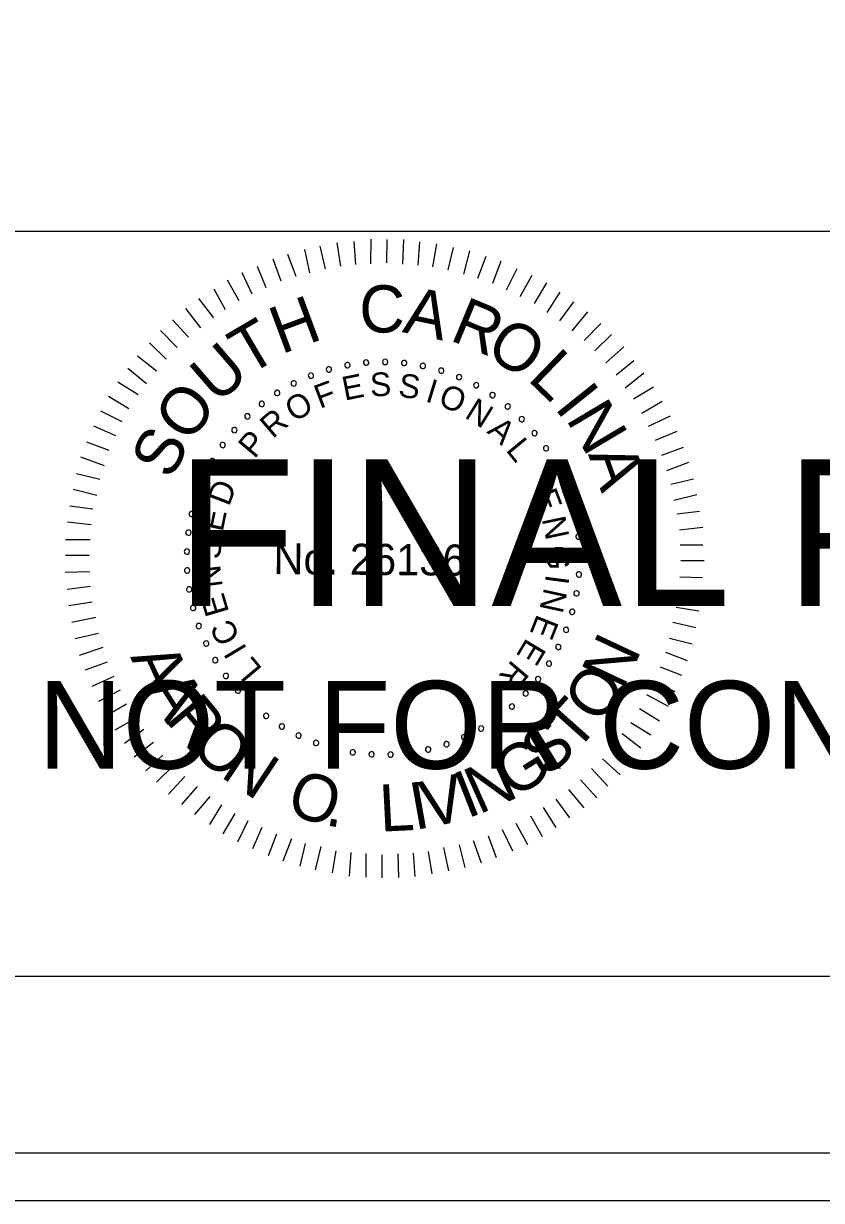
# Model space of a CAD drawing. Extents: x 967 to 1326, y 964 to 3704.
# Drawn here: x 1170.56 to 1189.3, y 1803.72 to 1831.36 of the extents above; entities that cross this region are included whole.
import ezdxf

# ---------------------------------------------------------------- set-up
doc = ezdxf.new("R2010")
doc.units = 0
for name, color, linetype in [('RD_SHT_Bndy', 7, 'Continuous'), ('RD_SHT_IplotShp', 7, 'Continuous'), ('RD_SHT_Misc1', 7, 'Continuous'), ('RD_SHT_Misc2', 7, 'Continuous'), ('RD_XS_TX_Station', 7, 'Continuous')]:
    doc.layers.add(name, color=color, linetype=linetype)

msp = doc.modelspace()

# ---------------------------------------------------------------- linework, layer by layer
at = {"layer": 'RD_SHT_Bndy'}
for p, q in [((996.114, 1826.486), (1323.886, 1826.486)), ((1323.886, 1808.983), (996.114, 1808.983))]:
    msp.add_line(p, q, dxfattribs=at)
at = {"layer": 'RD_SHT_IplotShp'}
for points in [[(967.409, 1803.72), (1326.285, 1803.72), (1326.285, 2023.72), (967.409, 2023.72)], [(988.525, 1804.84), (1326.285, 1804.84), (1326.285, 2022.6), (988.525, 2022.6)]]:
    msp.add_lwpolyline(points, close=True, dxfattribs=at)
at = {"layer": 'RD_SHT_Misc1'}
for p, q in [((1178.01, 1825.663), (1177.93, 1826.209)), ((1178.364, 1825.699), (1178.33, 1826.244)), ((1178.717, 1825.719), (1178.722, 1826.295)), ((1179.093, 1825.739), (1179.098, 1826.292)), ((1179.469, 1825.713), (1179.489, 1826.288)), ((1179.829, 1825.687), (1179.872, 1826.231)), ((1180.174, 1825.646), (1180.271, 1826.19)), ((1176.964, 1825.419), (1176.769, 1825.935)), ((1177.287, 1825.508), (1177.169, 1826.054)), ((1177.657, 1825.597), (1177.53, 1826.128)), ((1180.535, 1825.573), (1180.662, 1826.102)), ((1180.902, 1825.478), (1181.045, 1826.022)), ((1181.231, 1825.384), (1181.428, 1825.896)), ((1176.264, 1825.156), (1176.053, 1825.657)), ((1176.61, 1825.306), (1176.423, 1825.83)), ((1181.584, 1825.265), (1181.78, 1825.786)), ((1181.905, 1825.109), (1182.154, 1825.606)), ((1175.624, 1824.846), (1175.352, 1825.332)), ((1175.933, 1825.005), (1175.699, 1825.506)), ((1182.226, 1824.953), (1182.506, 1825.45)), ((1175.308, 1824.634), (1175.036, 1825.12)), ((1182.562, 1824.789), (1182.85, 1825.27)), ((1175.03, 1824.445), (1174.681, 1824.9)), ((1182.86, 1824.572), (1183.163, 1825.053)), ((1183.158, 1824.378), (1183.484, 1824.828)), ((1174.729, 1824.217), (1174.372, 1824.665)), ((1183.447, 1824.145), (1183.811, 1824.587)), ((1174.435, 1823.997), (1174.062, 1824.399)), ((1183.729, 1823.92), (1184.116, 1824.316)), ((1174.172, 1823.753), (1173.776, 1824.148)), ((1183.98, 1823.672), (1184.368, 1824.061)), ((1173.909, 1823.479), (1173.52, 1823.858)), ((1184.232, 1823.394), (1184.657, 1823.767)), ((1173.684, 1823.197), (1173.242, 1823.546)), ((1184.475, 1823.108), (1184.892, 1823.45)), ((1173.451, 1822.9), (1173.009, 1823.256)), ((1184.687, 1822.807), (1185.128, 1823.156)), ((1173.257, 1822.64), (1172.776, 1822.936)), ((1173.039, 1822.312), (1172.559, 1822.6)), ((1184.885, 1822.544), (1185.355, 1822.832)), ((1185.081, 1822.213), (1185.56, 1822.493)), ((1172.883, 1822.006), (1172.379, 1822.256)), ((1185.24, 1821.904), (1185.756, 1822.145)), ((1172.727, 1821.677), (1172.215, 1821.904)), ((1185.399, 1821.573), (1185.907, 1821.791)), ((1172.571, 1821.333), (1172.051, 1821.53)), ((1185.549, 1821.226), (1186.057, 1821.414)), ((1172.461, 1820.974), (1171.91, 1821.178)), ((1185.669, 1820.865), (1186.185, 1821.06)), ((1172.351, 1820.652), (1171.807, 1820.787)), ((1185.759, 1820.541), (1186.297, 1820.667)), ((1172.286, 1820.276), (1171.727, 1820.419)), ((1185.832, 1820.165), (1186.371, 1820.298)), ((1172.191, 1819.955), (1171.647, 1820.029)), ((1185.906, 1819.842), (1186.436, 1819.906)), ((1172.15, 1819.587), (1171.598, 1819.653)), ((1185.964, 1819.473), (1186.51, 1819.53)), ((1172.124, 1819.234), (1171.548, 1819.239)), ((1185.977, 1819.12), (1186.514, 1819.115)), ((1172.105, 1818.866), (1171.545, 1818.871)), ((1185.997, 1818.751), (1186.542, 1818.747)), ((1172.118, 1818.482), (1171.542, 1818.471)), ((1185.971, 1818.368), (1186.508, 1818.348)), ((1172.138, 1818.136), (1171.585, 1818.072)), ((1185.952, 1818.022), (1186.497, 1817.949)), ((1172.173, 1817.768), (1171.627, 1817.688)), ((1185.888, 1817.655), (1186.417, 1817.566)), ((1172.262, 1817.414), (1171.701, 1817.296)), ((1185.808, 1817.302), (1186.345, 1817.175)), ((1172.321, 1817.037), (1171.774, 1816.911)), ((1185.729, 1816.926), (1186.265, 1816.792)), ((1172.425, 1816.707), (1171.871, 1816.519)), ((1185.634, 1816.597), (1186.146, 1816.401)), ((1172.53, 1816.36), (1172.007, 1816.173)), ((1185.508, 1816.253), (1186.013, 1816.057)), ((1172.681, 1816.029), (1172.165, 1815.788)), ((1172.831, 1815.705), (1172.323, 1815.441)), ((1185.352, 1815.924), (1185.857, 1815.675)), ((1185.188, 1815.603), (1185.7, 1815.33)), ((1172.982, 1815.374), (1172.497, 1815.094)), ((1185.024, 1815.274), (1185.498, 1814.987)), ((1173.194, 1815.042), (1172.709, 1814.762)), ((1184.822, 1814.946), (1185.288, 1814.658)), ((1173.384, 1814.78), (1172.936, 1814.453)), ((1184.62, 1814.687), (1185.055, 1814.353)), ((1173.612, 1814.478), (1173.164, 1814.129)), ((1184.403, 1814.389), (1184.814, 1814.033)), ((1173.832, 1814.177), (1173.437, 1813.812)), ((1184.155, 1814.092), (1184.574, 1813.72)), ((1174.091, 1813.945), (1173.689, 1813.541)), ((1183.899, 1813.864), (1184.28, 1813.454)), ((1174.35, 1813.674), (1173.97, 1813.263)), ((1183.644, 1813.597), (1184.024, 1813.18)), ((1174.64, 1813.442), (1174.275, 1813.022)), ((1174.937, 1813.209), (1174.58, 1812.782)), ((1183.358, 1813.37), (1183.715, 1812.944)), ((1175.212, 1813.014), (1174.932, 1812.549)), ((1182.764, 1812.952), (1183.059, 1812.482)), ((1183.065, 1813.141), (1183.384, 1812.709)), ((1175.525, 1812.812), (1175.245, 1812.331)), ((1175.83, 1812.633), (1175.588, 1812.136)), ((1182.463, 1812.755), (1182.743, 1812.269)), ((1176.159, 1812.477), (1175.94, 1811.98)), ((1181.8, 1812.431), (1182.041, 1811.93)), ((1182.124, 1812.581), (1182.396, 1812.08)), ((1176.503, 1812.321), (1176.307, 1811.816)), ((1176.855, 1812.211), (1176.651, 1811.69)), ((1177.177, 1812.1), (1177.05, 1811.572)), ((1180.791, 1812.07), (1180.926, 1811.54)), ((1181.122, 1812.175), (1181.31, 1811.652)), ((1181.476, 1812.28), (1181.664, 1811.771)), ((1177.545, 1812.036), (1177.409, 1811.484)), ((1177.897, 1811.933), (1177.808, 1811.412)), ((1178.25, 1811.892), (1178.207, 1811.34)), ((1178.603, 1811.866), (1178.598, 1811.313)), ((1178.978, 1811.84), (1178.974, 1811.295)), ((1179.355, 1811.86), (1179.365, 1811.307)), ((1179.715, 1811.88), (1179.749, 1811.327)), ((1180.061, 1811.915), (1180.149, 1811.393)), ((1180.423, 1812.012), (1180.541, 1811.458))]:
    msp.add_line(p, q, dxfattribs=at)
for centre, start, end in [((1178.168, 1823.337), 10.6038, 190.6038), ((1178.609, 1823.397), 5.0653, 185.0653), ((1178.609, 1823.397), 185.0653, 5.0653), ((1179.055, 1823.414), 359.5268, 179.5268), ((1179.055, 1823.414), 179.5268, 359.5268), ((1179.5, 1823.388), 353.9884, 173.9884), ((1177.312, 1823.091), 21.6807, 201.6807), ((1177.734, 1823.235), 16.1422, 196.1422), ((1177.734, 1823.235), 196.1422, 16.1422), ((1178.168, 1823.337), 190.6038, 10.6038), ((1179.5, 1823.388), 173.9884, 353.9884), ((1179.94, 1823.319), 168.4499, 348.4499), ((1179.94, 1823.319), 348.4499, 168.4499), ((1180.372, 1823.208), 162.9114, 342.9114), ((1180.372, 1823.208), 342.9114, 162.9114), ((1180.79, 1823.056), 337.373, 157.373), ((1176.906, 1822.908), 27.2191, 207.2191), ((1176.906, 1822.908), 207.2191, 27.2191), ((1177.312, 1823.091), 201.6807, 21.6807), ((1180.79, 1823.056), 157.373, 337.373), ((1181.193, 1822.864), 151.8345, 331.8345), ((1181.193, 1822.864), 331.8345, 151.8345), ((1176.52, 1822.686), 32.7576, 212.7576), ((1176.52, 1822.686), 212.7576, 32.7576), ((1181.574, 1822.634), 146.2961, 326.2961), ((1181.574, 1822.634), 326.2961, 146.2961), ((1176.156, 1822.428), 38.2961, 218.2961), ((1176.156, 1822.428), 218.2961, 38.2961), ((1181.932, 1822.368), 140.7576, 320.7576), ((1181.932, 1822.368), 320.7576, 140.7576), ((1175.82, 1822.135), 43.8345, 223.8345), ((1175.82, 1822.135), 223.8345, 43.8345), ((1182.263, 1822.069), 135.2191, 315.2191), ((1182.263, 1822.069), 315.2191, 135.2191), ((1175.513, 1821.812), 49.373, 229.373), ((1175.513, 1821.812), 229.373, 49.373), ((1182.563, 1821.74), 129.6807, 309.6807), ((1182.563, 1821.74), 309.6807, 129.6807), ((1175.239, 1821.461), 54.9114, 234.9114), ((1175.239, 1821.461), 234.9114, 54.9114), ((1182.83, 1821.383), 124.1422, 304.1422), ((1182.83, 1821.383), 304.1422, 124.1422), ((1175, 1821.085), 60.4499, 240.4499), ((1175, 1821.085), 240.4499, 60.4499), ((1183.061, 1821.002), 118.6038, 298.6038), ((1183.061, 1821.002), 298.6038, 118.6038), ((1174.798, 1820.687), 65.9884, 245.9884), ((1174.798, 1820.687), 245.9884, 65.9884), ((1183.255, 1820.601), 113.0653, 293.0653), ((1183.255, 1820.601), 293.0653, 113.0653), ((1174.636, 1820.272), 71.5268, 251.5268), ((1174.636, 1820.272), 251.5268, 71.5268), ((1183.408, 1820.182), 107.5268, 287.5268), ((1183.408, 1820.182), 287.5268, 107.5268), ((1174.514, 1819.843), 77.0653, 257.0653), ((1174.514, 1819.843), 257.0653, 77.0653), ((1183.521, 1819.751), 101.9884, 281.9884), ((1183.521, 1819.751), 281.9884, 101.9884), ((1174.435, 1819.405), 82.6038, 262.6038), ((1174.435, 1819.405), 262.6038, 82.6038), ((1183.592, 1819.311), 96.4499, 276.4499), ((1183.592, 1819.311), 276.4499, 96.4499), ((1174.398, 1818.961), 88.1422, 268.1422), ((1174.398, 1818.961), 268.1422, 88.1422), ((1183.619, 1818.866), 90.9114, 270.9114), ((1183.619, 1818.866), 270.9114, 90.9114), ((1174.404, 1818.515), 93.6807, 273.6807), ((1174.404, 1818.515), 273.6807, 93.6807), ((1183.604, 1818.421), 85.373, 265.373), ((1183.604, 1818.421), 265.373, 85.373), ((1174.453, 1818.072), 99.2191, 279.2191), ((1174.453, 1818.072), 279.2191, 99.2191), ((1183.546, 1817.979), 79.8345, 259.8345), ((1183.546, 1817.979), 259.8345, 79.8345), ((1174.545, 1817.636), 104.7576, 284.7576), ((1174.545, 1817.636), 284.7576, 104.7576), ((1183.445, 1817.545), 74.2961, 254.2961), ((1183.445, 1817.545), 254.2961, 74.2961), ((1174.678, 1817.211), 110.2961, 290.2961), ((1174.678, 1817.211), 290.2961, 110.2961), ((1183.303, 1817.122), 68.7576, 248.7576), ((1183.303, 1817.122), 248.7576, 68.7576), ((1174.852, 1816.8), 115.8345, 295.8345), ((1174.852, 1816.8), 295.8345, 115.8345), ((1183.121, 1816.716), 63.2191, 243.2191), ((1183.121, 1816.716), 243.2191, 63.2191), ((1175.065, 1816.409), 121.373, 301.373), ((1175.065, 1816.409), 301.373, 121.373), ((1182.9, 1816.328), 57.6807, 237.6807), ((1182.9, 1816.328), 237.6807, 57.6807), ((1175.314, 1816.039), 126.9114, 306.9114), ((1175.314, 1816.039), 306.9114, 126.9114), ((1182.643, 1815.964), 52.1422, 232.1422), ((1182.643, 1815.964), 232.1422, 52.1422), ((1175.598, 1815.696), 132.4499, 312.4499), ((1175.598, 1815.696), 312.4499, 132.4499), ((1182.353, 1815.627), 46.6038, 226.6038), ((1182.353, 1815.627), 226.6038, 46.6038), ((1175.914, 1815.381), 137.9884, 317.9884), ((1175.914, 1815.381), 317.9884, 137.9884), ((1182.03, 1815.319), 41.0653, 221.0653), ((1176.258, 1815.099), 143.5268, 323.5268), ((1176.258, 1815.099), 323.5268, 143.5268), ((1181.68, 1815.043), 35.5268, 215.5268), ((1182.03, 1815.319), 221.0653, 41.0653), ((1176.629, 1814.851), 149.0653, 329.0653), ((1176.629, 1814.851), 329.0653, 149.0653), ((1181.305, 1814.803), 29.9884, 209.9884), ((1181.305, 1814.803), 209.9884, 29.9884), ((1181.68, 1815.043), 215.5268, 35.5268), ((1177.021, 1814.639), 154.6038, 334.6038), ((1177.021, 1814.639), 334.6038, 154.6038), ((1180.908, 1814.6), 24.4499, 204.4499), ((1180.908, 1814.6), 204.4499, 24.4499), ((1177.432, 1814.467), 160.1422, 340.1422), ((1177.432, 1814.467), 340.1422, 160.1422), ((1177.858, 1814.335), 165.6807, 345.6807), ((1177.858, 1814.335), 345.6807, 165.6807), ((1178.294, 1814.245), 351.2191, 171.2191), ((1179.627, 1814.232), 7.8345, 187.8345), ((1180.065, 1814.313), 13.373, 193.373), ((1180.065, 1814.313), 193.373, 13.373), ((1180.494, 1814.436), 18.9114, 198.9114), ((1180.494, 1814.436), 198.9114, 18.9114), ((1178.294, 1814.245), 171.2191, 351.2191), ((1178.737, 1814.198), 356.7576, 176.7576), ((1178.737, 1814.198), 176.7576, 356.7576), ((1179.183, 1814.193), 2.2961, 182.2961), ((1179.183, 1814.193), 182.2961, 2.2961), ((1179.627, 1814.232), 187.8345, 7.8345)]:
    msp.add_arc(centre, 0.0627, start, end, dxfattribs=at)
at = {"layer": 'RD_XS_TX_Station'}
msp.add_lwpolyline([(967.409, 1803.72), (1326.285, 1803.72), (1326.285, 2023.72), (967.409, 2023.72)], close=True, dxfattribs=at)

# ---------------------------------------------------------------- texts
at = {"layer": 'RD_SHT_Misc1'}
for s, height, rotation, p in [('C', 1.11, 359.5482, (1178.442, 1824.108)), ('A', 1.11, 348.1981, (1179.439, 1824.115)), ('H', 1.11, 20.3637, (1176.614, 1823.587)), ('R', 1.11, 337.4344, (1180.541, 1823.937)), ('T', 1.11, 30.4992, (1175.828, 1823.072)), ('O', 1.108, 326.5869, (1181.366, 1823.609)), ('U', 1.11, 40.8022, (1175.102, 1822.403)), ('L', 1.11, 315.9488, (1182.373, 1823.003)), ('E', 0.557, 11.4103, (1178.103, 1822.503)), ('S', 0.557, 2.208, (1178.709, 1822.601)), ('S', 0.557, 352.6608, (1179.346, 1822.599)), ('O', 1.11, 52.0267, (1174.435, 1821.474)), ('F', 0.557, 20.6127, (1177.52, 1822.309)), ('I', 0.557, 343.1136, (1179.975, 1822.491)), ('O', 0.557, 338.4392, (1180.274, 1822.401)), ('I', 1.11, 308.6613, (1183.011, 1822.338)), ('O', 0.557, 30.8477, (1176.917, 1821.987)), ('N', 0.557, 328.2042, (1180.896, 1822.12)), ('N', 1.11, 300.7037, (1183.285, 1822.075)), ('R', 0.557, 40.3949, (1176.415, 1821.594)), ('A', 0.557, 318.657, (1181.424, 1821.762)), ('S', 1.108, 63.2511, (1174.029, 1820.619)), ('P', 0.557, 49.9421, (1175.985, 1821.124)), ('L', 0.557, 309.4546, (1181.869, 1821.339)), ('A', 1.11, 289.4792, (1183.814, 1821.243)), ('D', 0.557, 69.0364, (1175.386, 1820.003)), ('E', 0.557, 291.049, (1182.53, 1820.307)), ('E', 0.557, 78.2388, (1175.238, 1819.407)), ('N', 0.557, 281.8466, (1182.728, 1819.726)), ('S', 0.557, 87.786, (1175.187, 1818.772)), ('No. 26136', 0.7311, 359.5268, (1176.429, 1818.43)), ('G', 0.557, 272.2995, (1182.833, 1819.097)), ('N', 0.557, 97.3332, (1175.242, 1818.137)), ('I', 0.557, 262.4084, (1182.83, 1818.437)), ('E', 0.557, 106.5355, (1175.394, 1817.541)), ('N', 0.557, 257.7339, (1182.789, 1818.127)), ('C', 0.557, 116.4266, (1175.661, 1816.938)), ('E', 0.557, 248.1867, (1182.628, 1817.511)), ('I', 0.557, 121.1011, (1175.823, 1816.67)), ('E', 0.557, 238.9844, (1182.378, 1816.949)), ('N', 1.105, 64.8922, (1184.632, 1815.684)), ('A', 1.105, 294.7297, (1173.062, 1816.486)), ('L', 0.557, 129.9595, (1176.187, 1816.204)), ('R', 0.557, 229.782, (1182.041, 1816.435)), ('O', 1.105, 56.2059, (1184.102, 1814.874)), ('A', 1.105, 302.2892, (1173.414, 1815.72)), ('R', 1.105, 309.8487, (1173.865, 1815.007)), ('T', 1.105, 48.2685, (1183.515, 1814.211)), ('O', 1.105, 317.7861, (1174.434, 1814.33)), ('S', 1.105, 40.3311, (1182.842, 1813.636)), ('N', 1.105, 326.4725, (1175.158, 1813.686)), ('G', 1.105, 32.0198, (1182.059, 1813.14)), ('N', 1.105, 24.0824, (1181.252, 1812.776)), ('O', 1.105, 342.3472, (1176.697, 1812.82)), ('V', 1.105, 12.7741, (1180.033, 1812.457)), ('I', 1.105, 21.4605, (1180.976, 1812.681)), ('L', 1.105, 2.9677, (1178.943, 1812.379)), ('I', 1.105, 10.1523, (1179.743, 1812.418)), ('.', 1.105, 351.0336, (1177.623, 1812.536))]:
    msp.add_text(s, height=height, rotation=rotation, dxfattribs=at).set_placement(p)
at = {"layer": 'RD_SHT_Misc2'}
for s, height, p in [('FINAL PLANS', 3.4375, (1174.145, 1817.685)), ('NOT FOR CONSTRUCTION', 2.0625, (1170.901, 1813.86))]:
    msp.add_text(s, height=height, dxfattribs=at).set_placement(p)

doc.saveas('drawing.dxf')
